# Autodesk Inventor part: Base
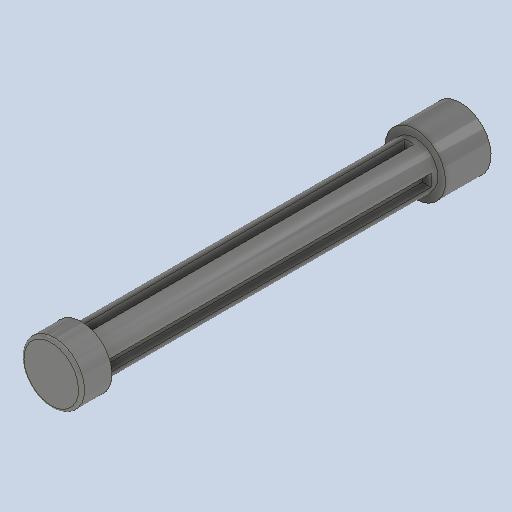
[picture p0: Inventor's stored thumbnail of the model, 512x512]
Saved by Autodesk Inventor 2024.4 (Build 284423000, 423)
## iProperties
Created: 2025-07
Part Number: Base
Material: Generic
Document SubType Name: Modeling
Designer: AdminForWorker
Density: 1 g/cm^3
Appearance: Default
Title: Base v2
Author: AdminForWorker
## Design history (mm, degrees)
feature "Body3"
body "Solid1"
